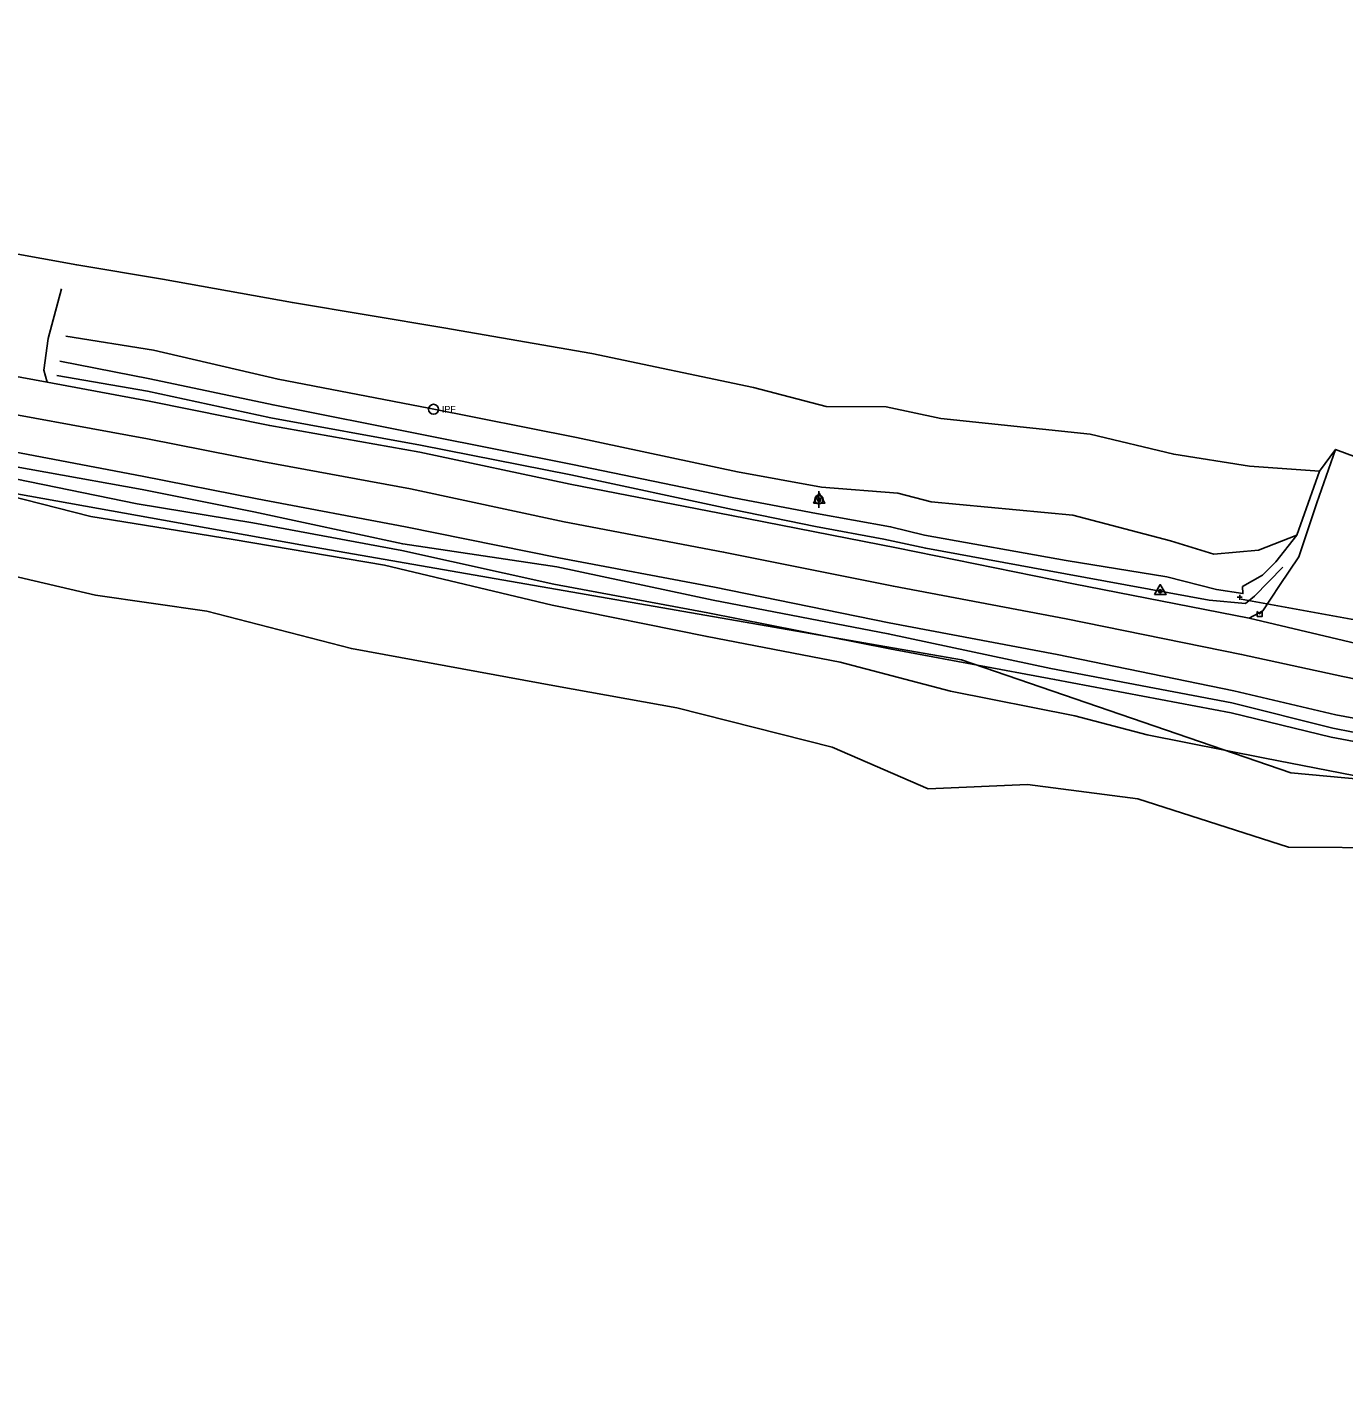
# Model space of a CAD drawing. Extents: x 1158469 to 1165378, y 609843 to 611748.
# Drawn here: x 1163418.6 to 1163813.4, y 610153.1 to 610560.2 of the extents above; entities that cross this region are included whole.
import ezdxf

# ---------------------------------------------------------------- set-up
doc = ezdxf.new("R2010")
doc.units = 0
for name, color, linetype in [('Exterior Boundary', 7, 'Continuous'), ('S_Control_Temp_Traverse', 7, 'Continuous'), ('S_Control_Traverse_Point', 7, 'Continuous'), ('S_Drainage_Culvert_Top', 7, 'Continuous'), ('S_Drainage_Invert', 7, 'Continuous'), ('S_Ground_Elevation', 7, 'Continuous'), ('S_Property_IronPipeFound', 7, 'Continuous'), ('S_Property_Mailbox', 7, 'Continuous'), ('S_Roadway_Centerline', 7, 'Continuous'), ('S_Roadway_Drive_Gravel', 7, 'Continuous'), ('S_Roadway_Edge_Pavement', 7, 'Continuous'), ('S_Roadway_Entr_Field_Wood', 7, 'Continuous'), ('S_Trees_TreeLine', 7, 'Continuous'), ('S_Utilities_Pole_Power', 7, 'Continuous')]:
    doc.layers.add(name, color=color, linetype=linetype)

msp = doc.modelspace()

# ---------------------------------------------------------------- linework, layer by layer
at = {"layer": 'Exterior Boundary'}
for points in [[(1163825.18, 610428.25), (1163810.95, 610433.6), (1163806.18, 610427.07), (1163785.16, 610428.54), (1163762.42, 610432.16), (1163737.34, 610438.11), (1163692.61, 610442.86), (1163676.17, 610446.36), (1163658.22, 610446.48), (1163636.47, 610452.14), (1163588, 610462.3), (1163543.54, 610470), (1163498.19, 610477.62), (1163459.19, 610484.67), (1163433.5, 610488.92), (1163361.04, 610502.07)], [(1163389.83, 610401.35), (1163439.18, 610389.84), (1163472.51, 610385.04), (1163515.89, 610373.87), (1163577.4, 610362.62), (1163613.4, 610356.11), (1163659.98, 610344.31), (1163688.84, 610331.83), (1163718.58, 610333.09), (1163751.67, 610328.84), (1163796.8, 610314.29), (1163829.15, 610314.08)]]:
    msp.add_lwpolyline(points, dxfattribs=at)
at = {"layer": 'S_Control_Temp_Traverse'}
for p, q in [((1163655.98, 610418.47), (1163656.23, 610418.47)), ((1163656.11, 610418.6), (1163656.11, 610418.35))]:
    msp.add_line(p, q, dxfattribs=at)
msp.add_lwpolyline([(1163654.38, 610417.47), (1163657.84, 610417.47), (1163656.11, 610420.47)], close=True, dxfattribs=at)
msp.add_circle((1163656.11, 610418.47), 0.5, dxfattribs=at)
at = {"layer": 'S_Control_Traverse_Point'}
for p, q in [((1163758.26, 610391.06), (1163758.51, 610391.06)), ((1163758.39, 610391.18), (1163758.39, 610390.93))]:
    msp.add_line(p, q, dxfattribs=at)
msp.add_lwpolyline([(1163756.66, 610390.06), (1163760.12, 610390.06), (1163758.39, 610393.06)], close=True, dxfattribs=at)
msp.add_circle((1163758.39, 610391.06), 0.5, dxfattribs=at)
at = {"layer": 'S_Drainage_Culvert_Top'}
msp.add_lwpolyline([(1163821.13, 610381.64), (1163782.69, 610388.72)], dxfattribs=at)
at = {"layer": 'S_Drainage_Invert'}
for p, q in [((1163781.46, 610389.28), (1163782.96, 610389.28)), ((1163782.21, 610390.03), (1163782.21, 610388.53))]:
    msp.add_line(p, q, dxfattribs=at)
at = {"layer": 'S_Ground_Elevation'}
for points in [[(1163806.18, 610427.07), (1163785.16, 610428.54), (1163762.42, 610432.16), (1163737.34, 610438.11), (1163692.61, 610442.86), (1163676.17, 610446.36), (1163658.22, 610446.48), (1163636.47, 610452.14), (1163588, 610462.3), (1163543.54, 610470), (1163498.19, 610477.62), (1163459.19, 610484.67), (1163433.5, 610488.92), (1163361.04, 610502.07), (1163307.63, 610510.96), (1163256.24, 610523.06), (1163214.87, 610533.83), (1163166.64, 610541.85), (1163118.08, 610553.15), (1163092.22, 610560.2), (1163097.08, 610534.57)], [(1163835.47, 610332.12), (1163789.78, 610340.97), (1163754.48, 610347.99), (1163732.73, 610353.73), (1163695.46, 610361.13), (1163662.45, 610369.82), (1163622.5, 610377.47), (1163576.02, 610386.9), (1163525.84, 610398.87), (1163480.43, 610406.56), (1163437.76, 610413.5), (1163397.67, 610423.69), (1163346.89, 610434.04), (1163295.83, 610444.31), (1163244.57, 610453.62), (1163201.2, 610458.95), (1163103.14, 610471.48), (1163068.93, 610471.67), (1163023.6, 610484.77), (1162985.89, 610490.99), (1162953.01, 610502.98)], [(1163829.15, 610314.08), (1163796.8, 610314.29), (1163751.67, 610328.84), (1163718.58, 610333.09), (1163688.84, 610331.83), (1163659.98, 610344.31), (1163613.4, 610356.11), (1163577.4, 610362.62), (1163515.89, 610373.87), (1163472.51, 610385.04), (1163439.18, 610389.84), (1163389.83, 610401.35), (1163342.83, 610404.81), (1163288.26, 610414.62), (1163245.37, 610428.91), (1163197.86, 610440.83), (1163102.54, 610451.72), (1163057.57, 610455.98), (1163025.8, 610467.8), (1162974.15, 610474.67), (1162950.55, 610478.5)], [(1163806.18, 610427.07), (1163799.34, 610407.88), (1163787.81, 610403.33), (1163774.48, 610402.19), (1163761.44, 610406.22), (1163732.22, 610413.86), (1163689.72, 610417.9), (1163679.69, 610420.42), (1163656.79, 610422.31), (1163631.6, 610426.88), (1163583.38, 610437.14), (1163539.11, 610445.92), (1163493.89, 610454.61), (1163456.48, 610463.35), (1163430.26, 610467.5)], [(1163806.18, 610427.07), (1163799.34, 610407.88), (1163793.02, 610399.83), (1163789.03, 610395.89), (1163783.07, 610392.46), (1163783.16, 610390.34), (1163775.28, 610391.63), (1163760.33, 610395.34), (1163730.17, 610400.31), (1163687.74, 610407.88), (1163677.53, 610410.42), (1163655.28, 610414.39), (1163630.52, 610419.1), (1163582.13, 610429.02), (1163537.51, 610437.94), (1163492.38, 610446.94), (1163455.38, 610454.74), (1163428.49, 610460)], [(1163795.19, 610398.24), (1163786.68, 610389.61), (1163783.92, 610387.36), (1163773.01, 610388.43), (1163729.95, 610396.31), (1163688.09, 610403.94), (1163675.47, 610406.7), (1163655.06, 610410.44), (1163630.1, 610415.61), (1163581.7, 610425.96), (1163536.58, 610434.84), (1163491.75, 610443.03), (1163454.76, 610451.01), (1163427.56, 610455.79)], [(1163779.89, 610357.63), (1163725.62, 610367.88), (1163676.83, 610378.31), (1163624.38, 610388.41), (1163577.47, 610398.36), (1163531.27, 610405.26), (1163486.61, 610414.88), (1163453.12, 610421.55), (1163395.29, 610431.98)], [(1163973.48, 610303.35), (1163959.4, 610307.45), (1163941.13, 610313.56), (1163909.8, 610321.77), (1163889.47, 610326.67), (1163861.86, 610334.59), (1163839.94, 610341.57), (1163809.67, 610347.31), (1163779.65, 610354.61), (1163726.69, 610364.63), (1163677.32, 610373.8), (1163622.69, 610384.57), (1163576.61, 610393.16), (1163531.02, 610403.24), (1163486.27, 610411.56), (1163451.68, 610417.28), (1163394.95, 610428.82)], [(1163779.89, 610357.63), (1163810.15, 610349.97)], [(1164520.77, 610202.93), (1164515.33, 610209.28), (1164493.38, 610214.1), (1164476.21, 610217.89), (1164467.58, 610219.08), (1164423.9, 610229.6), (1164397.15, 610234.48), (1164374.17, 610239.23), (1164343.27, 610245.58), (1164300.5, 610253.79), (1164258.79, 610262.51), (1164217.97, 610271.11), (1164184.42, 610277.79), (1164144.08, 610285.75), (1164112.82, 610291.92), (1164112.71, 610291.96), (1164073.57, 610299.64), (1164023.82, 610309.62), (1163973.46, 610318.76), (1163928.85, 610327.81), (1163885.4, 610335.83), (1163840.61, 610343.96), (1163810.15, 610349.97)]]:
    msp.add_lwpolyline(points, dxfattribs=at)
at = {"layer": 'S_Property_IronPipeFound'}
msp.add_circle((1163540.51, 610445.61), 1.5, dxfattribs=at)
at = {"layer": 'S_Property_Mailbox'}
msp.add_lwpolyline([(1163787.48, 610385.03), (1163787.48, 610383.53), (1163788.98, 610383.53), (1163788.98, 610385.03), (1163788.23, 610384.28)], close=True, dxfattribs=at)
at = {"layer": 'S_Roadway_Centerline'}
msp.add_lwpolyline([(1163843.92, 610359.23), (1163813.1, 610365.51), (1163782.78, 610372.1), (1163730.16, 610382.75), (1163678.39, 610392.55), (1163627.45, 610402.8), (1163579.67, 610411.92), (1163533.57, 610421.72), (1163489.57, 610429.88), (1163454.7, 610436.74), (1163397.92, 610447.15)], dxfattribs=at)
at = {"layer": 'S_Roadway_Drive_Gravel'}
msp.add_lwpolyline([(1163810.95, 610433.6), (1163805.38, 610417.54), (1163799.95, 610401.37), (1163794.11, 610392.81), (1163789.11, 610385.22), (1163785.01, 610382.97)], dxfattribs=at)
at = {"layer": 'S_Roadway_Edge_Pavement'}
for points in [[(1163820.93, 610374.47), (1163785.01, 610382.97), (1163732.38, 610393.27), (1163679.26, 610404.09), (1163629.86, 610413.79), (1163581.47, 610423.2), (1163536.41, 610432.75), (1163491.39, 610440.75), (1163455.22, 610448.04), (1163424.69, 610453.74), (1163400.64, 610458.12)], [(1163841.21, 610348.44), (1163811.04, 610354.03), (1163780.41, 610361.21), (1163727.45, 610372.05), (1163677.14, 610381.55), (1163624.7, 610392.26), (1163578.09, 610401.09), (1163532.07, 610410.34), (1163487.64, 610418.76), (1163453.12, 610425.57), (1163396.27, 610436.39)]]:
    msp.add_lwpolyline(points, dxfattribs=at)
at = {"layer": 'S_Roadway_Entr_Field_Wood'}
msp.add_lwpolyline([(1163424.69, 610453.74), (1163423.65, 610457.31), (1163424.94, 610466.89), (1163428.92, 610481.69)], dxfattribs=at)
at = {"layer": 'S_Trees_TreeLine'}
msp.add_lwpolyline([(1164496.37, 610153.1), (1164502.33, 610189.15), (1164371.9, 610237.25), (1164187.56, 610272.44), (1164065.59, 610298.24), (1163909.78, 610326.25), (1163797.57, 610336.57), (1163698.78, 610370.51), (1163500.7, 610405), (1163394.83, 610423.94)], dxfattribs=at)
at = {"layer": 'S_Utilities_Pole_Power'}
msp.add_line((1163656.04, 610421.07), (1163656.04, 610416.07), dxfattribs=at)
msp.add_circle((1163656.04, 610418.57), 1.25, dxfattribs=at)

# ---------------------------------------------------------------- texts
at = {"layer": 'S_Property_IronPipeFound'}
msp.add_text('IPF', height=2, dxfattribs=at).set_placement((1163543.01, 610444.61))

doc.saveas('drawing.dxf')
